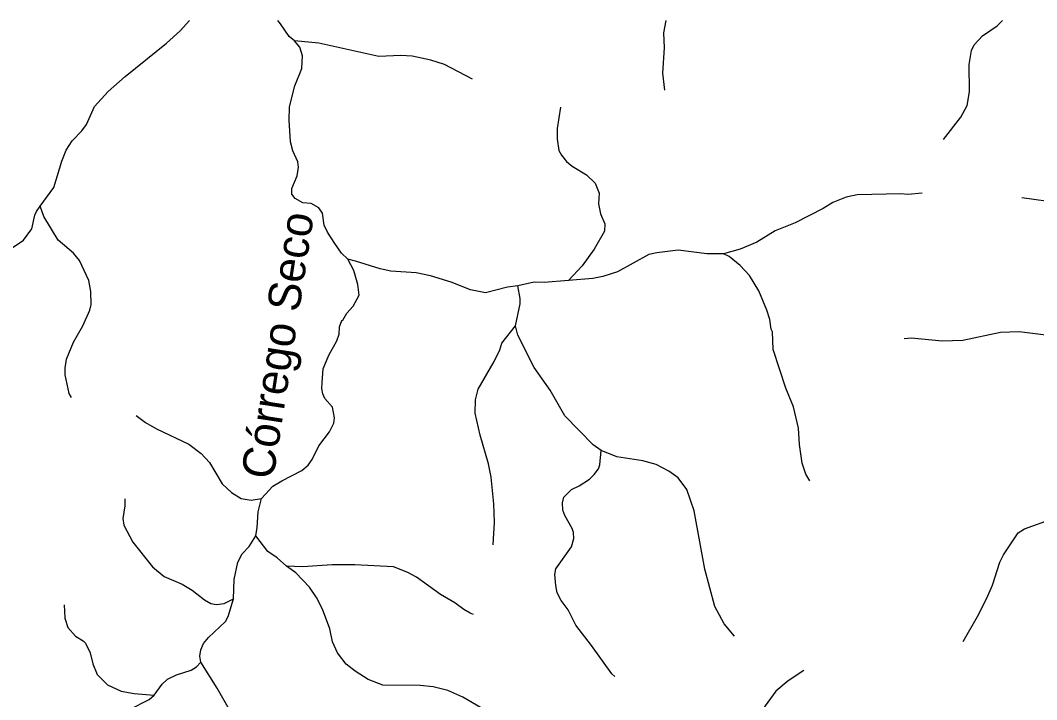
# Model space of a CAD drawing. Extents: x 500 to 555.2, y 9115.7 to 9171.
# Drawn here: x 507.19 to 513.43, y 9166.8 to 9170.97 of the extents above; entities that cross this region are included whole.
import ezdxf
from ezdxf.enums import TextEntityAlignment as Align

# ---------------------------------------------------------------- set-up
doc = ezdxf.new("R2010")
doc.units = 0
doc.header["$LTSCALE"] = 0.064
doc.layers.add('61', color=7, linetype='Continuous')
doc.layers.add('7', color=7, linetype='Continuous', lineweight=25)

msp = doc.modelspace()

# ---------------------------------------------------------------- linework, layer by layer
at = {"layer": '7'}
for points in [[(507.3079, 9169.8325), (507.391, 9169.9468), (507.4398, 9170.1095), (507.4667, 9170.1763), (507.5048, 9170.2336), (507.5627, 9170.2949), (507.5926, 9170.3349), (507.6406, 9170.4452), (507.7254, 9170.5359), (507.8299, 9170.628), (508.0842, 9170.8331), (508.1663, 9170.9101), (508.2252, 9170.9736)], [(508.8706, 9170.8482), (508.8371, 9170.8743), (508.7833, 9170.9513), (508.7678, 9170.9735)], [(511.1443, 9170.5456), (511.1324, 9170.6487), (511.1422, 9170.805), (511.139, 9170.8975), (511.1518, 9170.9731)], [(512.8564, 9170.2423), (512.963, 9170.3795), (513.0019, 9170.4501), (513.0154, 9170.5339), (513.0138, 9170.7017), (513.0275, 9170.7881), (513.0454, 9170.8225), (513.0968, 9170.8788), (513.1865, 9170.9392), (513.2181, 9170.9726)], [(509.1969, 9169.5064), (509.1589, 9169.5436), (509.1171, 9169.6024), (509.0722, 9169.6722), (509.0509, 9169.7165), (509.0408, 9169.7886), (509.0201, 9169.822), (508.9721, 9169.8492), (508.9203, 9169.8527), (508.8737, 9169.8805), (508.8526, 9169.907), (508.8526, 9169.9403), (508.8868, 9170.0184), (508.8933, 9170.0722), (508.8903, 9170.1057), (508.86, 9170.1728), (508.8445, 9170.2268), (508.8376, 9170.3613), (508.8393, 9170.4415), (508.8719, 9170.5721), (508.9147, 9170.6778), (508.9196, 9170.7558), (508.9027, 9170.8095), (508.8706, 9170.8482)], [(509.9624, 9170.6125), (509.791, 9170.7015), (509.7081, 9170.7282), (509.5927, 9170.7545), (509.5226, 9170.758), (509.3882, 9170.7516), (509.0188, 9170.8334), (508.8706, 9170.8482)], [(510.5044, 9170.4414), (510.4829, 9170.3102), (510.4829, 9170.2448), (510.4943, 9170.1749), (510.5094, 9170.1457), (510.5411, 9170.1061), (510.5751, 9170.0786), (510.6628, 9170.0248), (510.7156, 9169.9739), (510.7402, 9169.9124), (510.7372, 9169.8463), (510.7486, 9169.7854), (510.7764, 9169.7248), (510.7731, 9169.6795), (510.7095, 9169.5694), (510.637, 9169.4655), (510.5527, 9169.376)], [(512.7259, 9169.9122), (512.6377, 9169.9036), (512.5936, 9169.9084), (512.3253, 9169.9018), (512.2593, 9169.887), (512.176, 9169.8553), (512.1176, 9169.8187), (511.945, 9169.73), (511.8233, 9169.6806), (511.7087, 9169.6119), (511.6079, 9169.5689), (511.5057, 9169.54)], [(513.3376, 9169.8858), (513.5721, 9169.8525), (513.6502, 9169.8298), (513.8682, 9169.7938), (513.9561, 9169.7858), (514.0566, 9169.7607), (514.2571, 9169.7394), (514.3221, 9169.7166), (514.4519, 9169.6383), (514.57, 9169.5204), (514.633, 9169.4778), (514.6743, 9169.4618), (514.7045, 9169.4415)], [(507.0816, 9169.5274), (507.1237, 9169.5687), (507.2055, 9169.623), (507.2558, 9169.6929), (507.2744, 9169.7781), (507.2848, 9169.8007), (507.3079, 9169.8325)], [(507.4989, 9168.6584), (507.4854, 9168.6812), (507.4612, 9168.7966), (507.4606, 9168.8384), (507.4694, 9168.8935), (507.5123, 9168.998), (507.569, 9169.0983), (507.6116, 9169.1929), (507.6205, 9169.2282), (507.6189, 9169.3092), (507.6071, 9169.3758), (507.5486, 9169.4993), (507.5126, 9169.5438), (507.4181, 9169.6239), (507.3299, 9169.7696), (507.3079, 9169.8325)], [(511.5057, 9169.54), (511.4031, 9169.5394), (511.2265, 9169.5622), (511.0946, 9169.5458), (511.0466, 9169.5348), (510.8533, 9169.4301), (510.7633, 9169.4), (510.7016, 9169.388), (510.5527, 9169.376)], [(512.0345, 9168.1462), (512.0113, 9168.1867), (511.9887, 9168.255), (511.9725, 9168.3688), (511.9657, 9168.4693), (511.9344, 9168.6011), (511.8888, 9168.7159), (511.8107, 9168.9514), (511.8049, 9169.0607), (511.7968, 9169.0764), (511.7899, 9169.1364), (511.772, 9169.1948), (511.7212, 9169.3129), (511.6645, 9169.4061), (511.608, 9169.4687), (511.5391, 9169.5228), (511.5057, 9169.54)], [(509.1301, 9169.0062), (509.1442, 9169.0473), (509.1462, 9169.0906), (509.1602, 9169.1308), (509.166, 9169.1317), (509.192, 9169.1752), (509.2296, 9169.2179), (509.2671, 9169.2868), (509.2592, 9169.3516), (509.2345, 9169.4376), (509.1969, 9169.5064)], [(510.2409, 9169.3425), (510.1772, 9169.3356), (510.043, 9169.3003), (509.9514, 9169.319), (509.8316, 9169.3654), (509.7055, 9169.4051), (509.6178, 9169.4229), (509.4616, 9169.4328), (509.396, 9169.4473), (509.2437, 9169.4954), (509.1969, 9169.5064)], [(510.5527, 9169.376), (510.4031, 9169.3639), (510.342, 9169.3652), (510.2409, 9169.3425)], [(510.2281, 9169.0976), (510.2556, 9169.2327), (510.2565, 9169.266), (510.2409, 9169.3425)], [(510.0892, 9167.7529), (510.0989, 9167.8898), (510.094, 9168.0046), (510.0776, 9168.168), (510.061, 9168.2506), (510.0107, 9168.4266), (509.9795, 9168.5612), (509.981, 9168.6437), (509.9974, 9168.7093), (510.0954, 9168.8778), (510.1301, 9168.9505), (510.1436, 9168.9918), (510.2281, 9169.0976)], [(510.7531, 9168.3322), (510.7049, 9168.3674), (510.53, 9168.5442), (510.4404, 9168.7022), (510.3411, 9168.8418), (510.2424, 9169.041), (510.2281, 9169.0976)], [(512.6145, 9169.0203), (512.6593, 9169.023), (512.8477, 9169.0064), (512.9744, 9169.0096), (513.2073, 9169.0587), (513.3221, 9169.062), (513.5178, 9169.0391), (513.5938, 9169.0374), (513.7551, 9169.0133), (513.9429, 9169.0111), (514.1665, 9168.9933)], [(508.6661, 9168.0367), (508.7361, 9168.1123), (508.7918, 9168.1467), (508.9147, 9168.2091), (508.9528, 9168.2424), (508.9778, 9168.2778), (509.0197, 9168.3616), (509.0856, 9168.4476), (509.1115, 9168.5004), (509.1163, 9168.5329), (509.1034, 9168.5988), (509.0562, 9168.6514), (509.0429, 9168.6799), (509.0383, 9168.7129), (509.0394, 9168.7494), (509.0461, 9168.834), (509.0813, 9168.9178), (509.1301, 9169.0062)], [(507.8967, 9168.5473), (507.9547, 9168.5048), (508.0219, 9168.4659), (508.2207, 9168.3713), (508.2963, 9168.314), (508.3481, 9168.2585), (508.4247, 9168.1282), (508.4828, 9168.0734), (508.5418, 9168.0372), (508.6029, 9168.0271), (508.6661, 9168.0367)], [(510.8374, 9166.9449), (510.819, 9166.9603), (510.6944, 9167.1346), (510.5971, 9167.2602), (510.55, 9167.3543), (510.5074, 9167.4104), (510.4839, 9167.4584), (510.4745, 9167.5035), (510.4698, 9167.5697), (510.4744, 9167.6049), (510.5717, 9167.741), (510.5861, 9167.7908), (510.5832, 9167.828), (510.5751, 9167.8536), (510.5307, 9167.9329), (510.5175, 9167.9665), (510.5158, 9168.0111), (510.5236, 9168.0454), (510.5703, 9168.0927), (510.6189, 9168.1157), (510.6827, 9168.157), (510.7112, 9168.1849), (510.7366, 9168.22), (510.7445, 9168.2444), (510.7531, 9168.3322)], [(511.5727, 9167.1923), (511.5083, 9167.2687), (511.4523, 9167.3742), (511.3897, 9167.6044), (511.3241, 9167.9613), (511.2797, 9168.0932), (511.2259, 9168.1646), (511.1701, 9168.2057), (511.0911, 9168.2461), (511.0099, 9168.268), (510.85, 9168.2923), (510.7531, 9168.3322)], [(508.6312, 9167.8087), (508.6409, 9167.8598), (508.6474, 9167.9549), (508.6661, 9168.0367)], [(507.8266, 9168.0363), (507.8264, 9167.9925), (507.8141, 9167.9148), (507.8211, 9167.8737), (507.876, 9167.7684), (507.9982, 9167.6181), (508.0691, 9167.5578), (508.1793, 9167.5122), (508.241, 9167.4755), (508.3174, 9167.4156), (508.3548, 9167.3934), (508.3904, 9167.3858), (508.4374, 9167.3921), (508.4946, 9167.421)], [(512.9775, 9167.1598), (513.0661, 9167.3119), (513.1231, 9167.4255), (513.1565, 9167.5059), (513.2029, 9167.6457), (513.2254, 9167.6923), (513.3145, 9167.8258), (513.3534, 9167.8507), (513.5361, 9167.9175), (513.5965, 9167.9571), (513.627, 9168.0161)], [(508.4946, 9167.421), (508.4997, 9167.5408), (508.5225, 9167.6458), (508.5487, 9167.6983), (508.5902, 9167.7421), (508.6312, 9167.8087)], [(508.8198, 9167.6219), (508.7632, 9167.673), (508.7064, 9167.7121), (508.6312, 9167.8087)], [(509.9691, 9167.326), (509.9486, 9167.3341), (509.9102, 9167.3566), (509.8555, 9167.3964), (509.7667, 9167.4486), (509.6184, 9167.5544), (509.5659, 9167.5828), (509.478, 9167.6182), (509.2412, 9167.6301), (509.1, 9167.63), (508.9178, 9167.6169), (508.8198, 9167.6219)], [(510.6323, 9166.6683), (510.5014, 9166.6292), (510.3954, 9166.628), (510.0586, 9166.7342), (510.0126, 9166.7538), (509.9044, 9166.8177), (509.8113, 9166.8591), (509.7207, 9166.8803), (509.6413, 9166.8886), (509.4117, 9166.8915), (509.3225, 9166.9255), (509.2416, 9166.9763), (509.188, 9167.0206), (509.1342, 9167.0893), (509.1021, 9167.1571), (509.0865, 9167.2376), (509.0426, 9167.3577), (509.0057, 9167.4295), (508.9622, 9167.4921), (508.8769, 9167.5808), (508.8198, 9167.6219)], [(508.295, 9167.0325), (508.2889, 9167.0688), (508.295, 9167.1075), (508.3109, 9167.1473), (508.3412, 9167.1841), (508.4451, 9167.2818), (508.4631, 9167.3128), (508.4946, 9167.421)], [(507.4541, 9167.385), (507.4598, 9167.3025), (507.4764, 9167.2455), (507.5233, 9167.1925), (507.5717, 9167.1638), (507.5857, 9167.1498), (507.6151, 9167.0899), (507.6308, 9167.0219), (507.6583, 9166.9575), (507.7211, 9166.8933), (507.8045, 9166.8553), (507.8849, 9166.8391), (508.007, 9166.8296)], [(508.007, 9166.8296), (508.0569, 9166.8967), (508.0886, 9166.9282), (508.1449, 9166.9556), (508.2346, 9166.9825), (508.2681, 9167.0032), (508.295, 9167.0325)], [(508.6071, 9166.4352), (508.5947, 9166.4762), (508.5675, 9166.5269), (508.5243, 9166.6458), (508.3944, 9166.8728), (508.295, 9167.0325)], [(511.9982, 9166.9807), (511.9021, 9166.9185), (511.8274, 9166.8537), (511.7606, 9166.7639), (511.7232, 9166.7038), (511.6988, 9166.647), (511.6871, 9166.5986), (511.6819, 9166.4299), (511.6212, 9166.277), (511.587, 9166.2231), (511.5618, 9166.2035)], [(507.6657, 9166.749), (507.8298, 9166.7361), (507.8569, 9166.7423), (507.9761, 9166.8034), (508.007, 9166.8296)]]:
    msp.add_lwpolyline(points, dxfattribs=at)

# ---------------------------------------------------------------- texts
at = {"layer": '61'}
msp.add_text('Córrego Seco', height=0.2, rotation=81.254, dxfattribs=at).set_placement((508.8639, 9168.9636), align=Align.CENTER)

doc.saveas('drawing.dxf')
